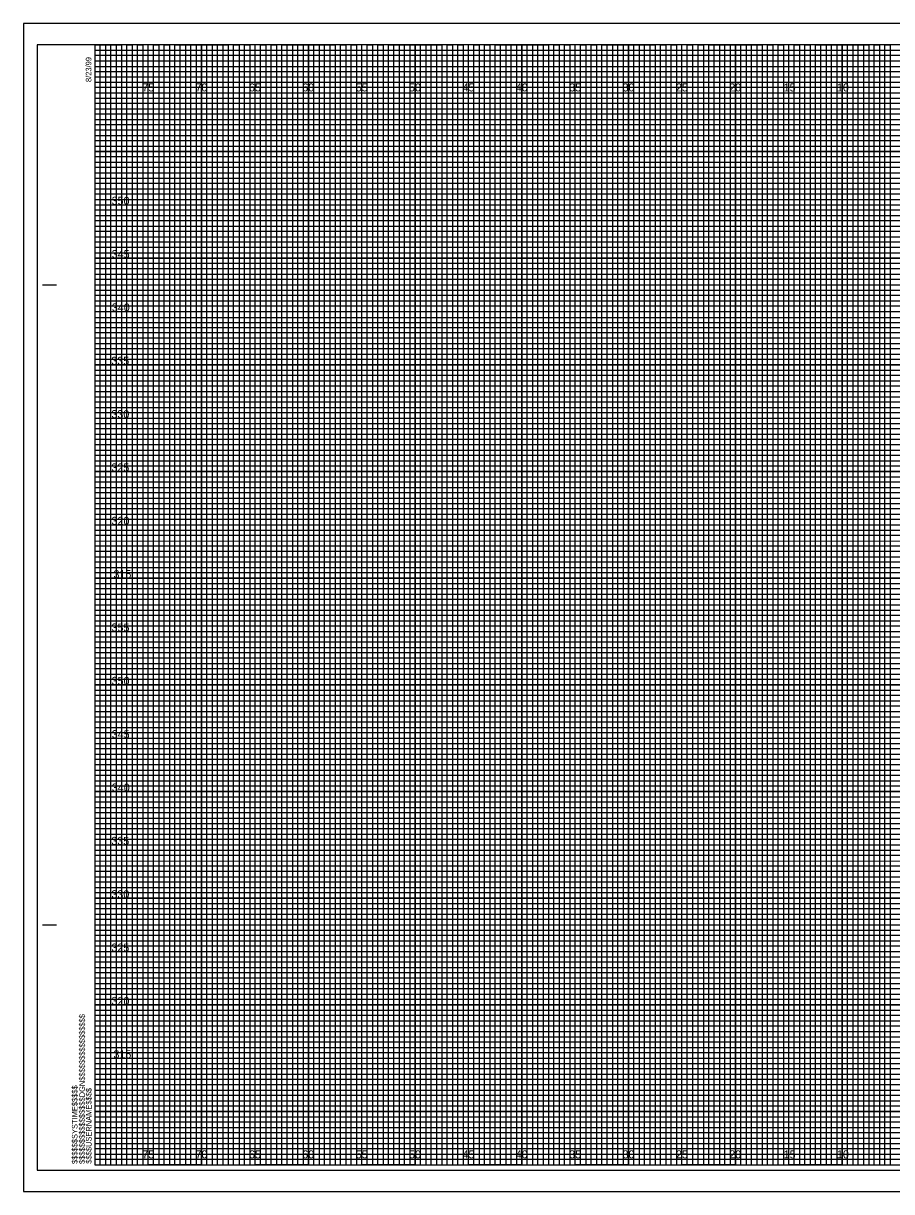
# Model space of a CAD drawing. Extents: x -7 to 162, y -2 to 327.
# Drawn here: x -6.7 to 74.6, y 107.5 to 217 of the extents above; entities that cross this region are included whole.
import ezdxf

# ---------------------------------------------------------------- set-up
doc = ezdxf.new("R2010")
doc.units = 0
for name, color, linetype in [('Exist Cross Section Cell', 7, 'Continuous'), ('Exist XS Center Line Elevation Label', 7, 'Continuous'), ('Exist XS Ground Line', 7, 'Continuous'), ('Old_Level_1', 7, 'Continuous'), ('Prop XS Bridge', 7, 'Continuous'), ('Prop XS Ditch Standard Text', 7, 'Continuous'), ('Prop XS EOT Tick Mark', 7, 'Continuous'), ('Prop XS Finish Grade Earthwork', 7, 'Continuous'), ('Prop XS Label Text', 7, 'Continuous'), ('Prop XS Subgrade', 7, 'Continuous'), ('Scratch_Level_3', 7, 'Continuous')]:
    doc.layers.add(name, color=color, linetype=linetype)

msp = doc.modelspace()

# ---------------------------------------------------------------- linework, layer by layer
at = {"layer": 'Exist XS Center Line Elevation Label'}
for points in [[(0, 215), (2.5, 215), (2.5, 110), (7.5, 110), (7.5, 215), (12.5, 215), (12.5, 110), (17.5, 110), (17.5, 215), (22.5, 215), (22.5, 110), (27.5, 110), (27.5, 215), (32.5, 215), (32.5, 110), (37.5, 110), (37.5, 215), (42.5, 215), (42.5, 110), (47.5, 110), (47.5, 215), (52.5, 215), (52.5, 110), (57.5, 110), (57.5, 215), (62.5, 215), (62.5, 110), (67.5, 110), (67.5, 215), (72.5, 215), (72.5, 110), (77.5, 110)], [(0, 212.5), (137.5, 212.5)], [(0, 202.5), (160, 202.5), (160, 207.5), (0, 207.5)], [(0, 192.5), (160, 192.5), (160, 197.5), (0, 197.5)], [(0, 182.5), (160, 182.5), (160, 187.5), (0, 187.5)], [(0, 172.5), (160, 172.5), (160, 177.5), (0, 177.5)], [(0, 162.5), (160, 162.5), (160, 167.5), (0, 167.5)], [(0, 152.5), (160, 152.5), (160, 157.5), (0, 157.5)], [(0, 142.5), (160, 142.5), (160, 147.5), (0, 147.5)], [(0, 132.5), (160, 132.5), (160, 137.5), (0, 137.5)], [(0, 122.5), (160, 122.5), (160, 127.5), (0, 127.5)], [(0, 112.5), (160, 112.5), (160, 117.5), (0, 117.5)]]:
    msp.add_lwpolyline(points, dxfattribs=at)
at = {"layer": 'Exist XS Ground Line'}
for p, q in [((5, 215), (0, 215)), ((5, 110), (5, 215)), ((15, 215), (10, 215)), ((10, 215), (10, 110)), ((15, 110), (15, 215)), ((25, 215), (20, 215)), ((20, 215), (20, 110)), ((25, 110), (25, 215)), ((35, 215), (30, 215)), ((30, 215), (30, 110)), ((35, 110), (35, 215)), ((45, 215), (40, 215)), ((40, 215), (40, 110)), ((45, 110), (45, 215)), ((55, 215), (50, 215)), ((50, 215), (50, 110)), ((55, 110), (55, 215)), ((65, 215), (60, 215)), ((60, 215), (60, 110)), ((65, 110), (65, 215)), ((75, 215), (70, 215)), ((70, 215), (70, 110)), ((10, 110), (5, 110)), ((20, 110), (15, 110)), ((30, 110), (25, 110)), ((40, 110), (35, 110)), ((50, 110), (45, 110)), ((60, 110), (55, 110)), ((70, 110), (65, 110))]:
    msp.add_line(p, q, dxfattribs=at)
for points in [[(0, 210), (160, 210), (160, 205), (0, 205)], [(0, 200), (160, 200), (160, 195), (0, 195)], [(0, 190), (160, 190), (160, 185), (0, 185)], [(0, 180), (160, 180), (160, 175), (0, 175)], [(0, 170), (160, 170), (160, 165), (0, 165)], [(0, 160), (160, 160), (160, 155), (0, 155)], [(0, 150), (160, 150), (160, 145), (0, 145)], [(0, 140), (160, 140), (160, 135), (0, 135)], [(0, 130), (160, 130), (160, 125), (0, 125)], [(0, 120), (160, 120), (160, 115), (0, 115)]]:
    msp.add_lwpolyline(points, dxfattribs=at)
at = {"layer": 'Old_Level_1'}
msp.add_lwpolyline([(-5.4, 109.5), (161.2, 109.5), (161.2, 215), (-5.4, 215)], close=True, dxfattribs=at)
at = {"layer": 'Prop XS Bridge'}
for p, q in [((5, 110), (5, 215)), ((10, 110), (10, 215)), ((15, 110), (15, 215)), ((20, 110), (20, 215)), ((25, 110), (25, 215)), ((30, 110), (30, 215)), ((35, 110), (35, 215)), ((40, 110), (40, 215)), ((45, 110), (45, 215)), ((50, 110), (50, 215)), ((55, 110), (55, 215)), ((60, 110), (60, 215)), ((65, 110), (65, 215)), ((70, 110), (70, 215)), ((0, 210), (160, 210)), ((0, 205), (160, 205)), ((0, 200), (160, 200)), ((0, 195), (160, 195)), ((0, 190), (160, 190)), ((0, 185), (160, 185)), ((0, 180), (160, 180)), ((0, 175), (160, 175)), ((0, 170), (160, 170)), ((0, 165), (160, 165)), ((0, 160), (160, 160)), ((0, 155), (160, 155)), ((0, 150), (160, 150)), ((0, 145), (160, 145)), ((0, 140), (160, 140)), ((0, 135), (160, 135)), ((0, 130), (160, 130)), ((0, 125), (160, 125)), ((0, 120), (160, 120)), ((0, 115), (160, 115))]:
    msp.add_line(p, q, dxfattribs=at)
at = {"layer": 'Prop XS EOT Tick Mark'}
for p, q in [((-4.9, 192.5), (-3.65, 192.5)), ((-4.85, 192.5), (-3.6, 192.5)), ((-4.9, 132.5), (-3.65, 132.5)), ((-4.85, 132.5), (-3.6, 132.5)), ((0, 110), (0, 110)), ((0, 110), (0, 110)), ((0, 110), (0, 110)), ((0, 110), (0, 110)), ((0, 110), (0, 110)), ((0, 110), (0, 110)), ((0, 110), (0, 110))]:
    msp.add_line(p, q, dxfattribs=at)
msp.add_lwpolyline([(160, 215), (0, 215), (0, 110), (160, 110)], close=True, dxfattribs=at)
at = {"layer": 'Prop XS Finish Grade Earthwork'}
for p, q in [((161.65, 217), (-6.7, 217)), ((-6.7, 217), (-6.7, 107.5)), ((-6.7, 107.5), (161.65, 107.5))]:
    msp.add_line(p, q, dxfattribs=at)
at = {"layer": 'Prop XS Label Text'}
for points in [[(0, 110), (0.5, 110), (0.5, 215), (1, 215), (1, 110)], [(1, 110), (1.5, 110), (1.5, 215), (2, 215), (2, 110)], [(2.5, 110), (3, 110), (3, 215), (3.5, 215), (3.5, 110)], [(3.5, 110), (4, 110), (4, 215), (4.5, 215), (4.5, 110)], [(5, 110), (5.5, 110), (5.5, 215), (6, 215), (6, 110)], [(6, 110), (6.5, 110), (6.5, 215), (7, 215), (7, 110)], [(7.5, 110), (8, 110), (8, 215), (8.5, 215), (8.5, 110)], [(8.5, 110), (9, 110), (9, 215), (9.5, 215), (9.5, 110)], [(10, 110), (10.5, 110), (10.5, 215), (11, 215), (11, 110)], [(11, 110), (11.5, 110), (11.5, 215), (12, 215), (12, 110)], [(12.5, 110), (13, 110), (13, 215), (13.5, 215), (13.5, 110)], [(13.5, 110), (14, 110), (14, 215), (14.5, 215), (14.5, 110)], [(15, 110), (15.5, 110), (15.5, 215), (16, 215), (16, 110)], [(16, 110), (16.5, 110), (16.5, 215), (17, 215), (17, 110)], [(17.5, 110), (18, 110), (18, 215), (18.5, 215), (18.5, 110)], [(18.5, 110), (19, 110), (19, 215), (19.5, 215), (19.5, 110)], [(20, 110), (20.5, 110), (20.5, 215), (21, 215), (21, 110)], [(21, 110), (21.5, 110), (21.5, 215), (22, 215), (22, 110)], [(22.5, 110), (23, 110), (23, 215), (23.5, 215), (23.5, 110)], [(23.5, 110), (24, 110), (24, 215), (24.5, 215), (24.5, 110)], [(25, 110), (25.5, 110), (25.5, 215), (26, 215), (26, 110)], [(26, 110), (26.5, 110), (26.5, 215), (27, 215), (27, 110)], [(27.5, 110), (28, 110), (28, 215), (28.5, 215), (28.5, 110)], [(28.5, 110), (29, 110), (29, 215), (29.5, 215), (29.5, 110)], [(30, 110), (30.5, 110), (30.5, 215), (31, 215), (31, 110)], [(31, 110), (31.5, 110), (31.5, 215), (32, 215), (32, 110)], [(32.5, 110), (33, 110), (33, 215), (33.5, 215), (33.5, 110)], [(33.5, 110), (34, 110), (34, 215), (34.5, 215), (34.5, 110)], [(35, 110), (35.5, 110), (35.5, 215), (36, 215), (36, 110)], [(36, 110), (36.5, 110), (36.5, 215), (37, 215), (37, 110)], [(37.5, 110), (38, 110), (38, 215), (38.5, 215), (38.5, 110)], [(38.5, 110), (39, 110), (39, 215), (39.5, 215), (39.5, 110)], [(40, 110), (40.5, 110), (40.5, 215), (41, 215), (41, 110)], [(41, 110), (41.5, 110), (41.5, 215), (42, 215), (42, 110)], [(42.5, 110), (43, 110), (43, 215), (43.5, 215), (43.5, 110)], [(43.5, 110), (44, 110), (44, 215), (44.5, 215), (44.5, 110)], [(45, 110), (45.5, 110), (45.5, 215), (46, 215), (46, 110)], [(46, 110), (46.5, 110), (46.5, 215), (47, 215), (47, 110)], [(47.5, 110), (48, 110), (48, 215), (48.5, 215), (48.5, 110)], [(48.5, 110), (49, 110), (49, 215), (49.5, 215), (49.5, 110)], [(50, 110), (50.5, 110), (50.5, 215), (51, 215), (51, 110)], [(51, 110), (51.5, 110), (51.5, 215), (52, 215), (52, 110)], [(52.5, 110), (53, 110), (53, 215), (53.5, 215), (53.5, 110)], [(53.5, 110), (54, 110), (54, 215), (54.5, 215), (54.5, 110)], [(55, 110), (55.5, 110), (55.5, 215), (56, 215), (56, 110)], [(56, 110), (56.5, 110), (56.5, 215), (57, 215), (57, 110)], [(57.5, 110), (58, 110), (58, 215), (58.5, 215), (58.5, 110)], [(58.5, 110), (59, 110), (59, 215), (59.5, 215), (59.5, 110)], [(60, 110), (60.5, 110), (60.5, 215), (61, 215), (61, 110)], [(61, 110), (61.5, 110), (61.5, 215), (62, 215), (62, 110)], [(62.5, 110), (63, 110), (63, 215), (63.5, 215), (63.5, 110)], [(63.5, 110), (64, 110), (64, 215), (64.5, 215), (64.5, 110)], [(65, 110), (65.5, 110), (65.5, 215), (66, 215), (66, 110)], [(66, 110), (66.5, 110), (66.5, 215), (67, 215), (67, 110)], [(67.5, 110), (68, 110), (68, 215), (68.5, 215), (68.5, 110)], [(68.5, 110), (69, 110), (69, 215), (69.5, 215), (69.5, 110)], [(70, 110), (70.5, 110), (70.5, 215), (71, 215), (71, 110)], [(71, 110), (71.5, 110), (71.5, 215), (72, 215), (72, 110)], [(72.5, 110), (73, 110), (73, 215), (73.5, 215), (73.5, 110)], [(73.5, 110), (74, 110), (74, 215), (74.5, 215), (74.5, 110)]]:
    msp.add_lwpolyline(points, dxfattribs=at)
at = {"layer": 'Prop XS Subgrade'}
msp.add_lwpolyline([(-6.7, 107.5), (161.65, 107.5), (161.65, 217), (-6.7, 217)], close=True, dxfattribs=at)
at = {"layer": 'Scratch_Level_3'}
for p, q in [((0, 214.5), (130, 214.5)), ((130, 213.99), (0, 213.99)), ((0, 213.99), (0, 213.5)), ((0, 213.5), (130, 213.5)), ((130, 212.94), (0, 212.94)), ((0, 212.94), (0, 212)), ((0, 212), (160, 212))]:
    msp.add_line(p, q, dxfattribs=at)
for points in [[(0, 211.5), (135, 211.5), (160, 211.5), (160, 211), (0, 211)], [(0, 210.5), (160, 210.5), (160, 209.5), (0, 209.5)], [(0, 209), (160, 209), (160, 208.5), (0, 208.49)], [(0, 208), (160, 208), (160, 207), (0, 207)], [(0, 206.5), (160, 206.5), (160, 206), (0, 206)], [(0, 205.5), (160, 205.5), (160, 204.5), (0, 204.5)], [(0, 204), (160, 204), (160, 203.5), (0, 203.5)], [(0, 203), (160, 203), (160, 202), (0, 202)], [(0, 201.5), (160, 201.5), (160, 201), (0, 201)], [(0, 200.5), (160, 200.5), (160, 199.5), (0, 199.5)], [(0, 199), (160, 199), (160, 198.5), (0, 198.5)], [(0, 198), (160, 198), (160, 196.97), (160, 196.5), (160, 196), (0, 196)], [(0, 197), (160, 197), (160, 196.5), (0, 196.5)], [(0, 195.5), (160, 195.5), (160, 194.5), (0, 194.52)], [(0, 194.52), (160, 194.5), (160, 194), (0, 194)], [(0, 193.5), (160, 193.5), (160, 193), (0, 193)], [(0, 192), (160, 192), (160, 191.5), (0, 191.5)], [(0, 191), (160, 191), (160, 190.5), (0, 190.5)], [(-0.04, 189.44), (160, 189.44), (160, 188.94), (-0.04, 188.94)], [(0, 188.5), (160, 188.5), (160, 188), (0, 188)], [(0, 187), (160, 187), (160, 186.5), (0, 186.5)], [(0, 186), (160, 186), (160, 185.5), (0, 185.5)], [(0, 184.5), (160, 184.5), (160, 184), (0, 184)], [(0, 183.5), (160, 183.5), (160, 183), (0, 183)], [(0, 182), (160, 182), (160, 181.5), (0, 181.5)], [(0, 181), (160, 181), (160, 180.5), (0, 180.5)], [(0, 179.5), (160, 179.5), (160, 178.99), (0, 179)], [(0, 178.5), (160, 178.5), (160, 178), (0, 178)], [(0, 177), (160, 177), (160, 176.5), (0, 176.5)], [(0, 176), (160, 176), (160, 175.5), (0, 175.5)], [(0, 174.5), (160, 174.5), (160, 174), (0, 174)], [(0, 173.5), (160, 173.5), (160, 173), (0, 173)], [(0, 172), (160, 172), (160, 171.5), (0, 171.5)], [(0, 171), (160, 171), (160, 170.5), (0, 170.5)], [(0, 169.5), (160, 169.5), (160, 169), (0, 169)], [(0, 168.5), (160.03, 168.46), (160, 168), (0, 168)], [(0, 167), (160, 167), (160, 166.5), (0, 166.5)], [(0, 166), (160, 166), (160, 165.5), (0, 165.5)], [(0, 164.5), (160, 164.5), (160, 164), (0, 164)], [(0, 163.5), (160, 163.5), (160, 163), (0, 163)], [(0, 162), (160, 162), (160, 161.5), (0, 161.5)], [(0, 161), (160, 161), (160, 160.5), (0, 160.5)], [(0, 159.5), (160, 159.5), (160, 159), (0, 159)], [(0, 158.5), (160, 158.5), (160, 158), (0, 158)], [(0, 157), (160, 157), (160, 156.5), (0, 156.5)], [(0, 156), (160, 156), (160, 155.5), (0, 155.5)], [(0, 154.5), (160, 154.5), (160, 154), (0, 154)], [(0, 153.5), (160, 153.5), (160, 153), (0, 153)], [(0, 152), (160, 152), (160, 151.5), (0, 151.5)], [(0, 151), (160, 151), (160, 150.5), (0, 150.5)], [(0, 149.5), (160, 149.5), (160, 148.99), (0, 149)], [(0, 148.5), (160, 148.5), (160, 148), (0, 148)], [(0, 147), (160, 147), (160, 146.5), (0, 146.5)], [(0, 146), (160, 146), (160, 145.5), (0, 145.5)], [(0, 144.5), (160, 144.5), (160, 144), (0, 144)], [(0, 143.5), (160, 143.5), (160, 143), (0, 143)], [(0, 142), (160, 142), (160, 141.5), (0, 141.5)], [(0, 141), (160, 141), (160, 140.5), (0, 140.5)], [(0, 139.5), (160, 139.5), (160, 139), (0, 139)], [(0, 138.5), (160.03, 138.46), (160, 138), (0, 138)], [(0, 137), (160, 137), (160, 136.5), (0, 136.5)], [(0, 136), (160, 136), (160, 135.5), (0, 135.5)], [(0, 134.5), (160, 134.5), (160, 134), (0, 134)], [(0, 133.5), (160, 133.5), (160, 133), (0, 133)], [(0, 132), (160, 132), (160, 131.5), (0, 131.5)], [(0, 131), (160, 131), (160, 130.5), (0, 130.5)], [(0, 129.5), (160, 129.5), (160, 129), (0, 129)], [(0, 128.5), (160, 128.5), (160, 128), (0, 128)], [(0, 127), (160, 127), (160, 126.5), (0, 126.5)], [(0, 126), (160, 126), (160, 125.5), (0, 125.5)], [(0, 124.5), (160, 124.5), (160, 124), (0, 124)], [(0, 123.5), (160, 123.5), (160, 123), (0, 123)], [(0, 122), (160, 122), (160, 121.5), (0, 121.5)], [(0, 121), (160, 121), (160, 120.5), (0, 120.5)], [(0, 119.5), (160, 119.5), (160, 119), (0, 119)], [(0, 118.5), (160, 118.5), (160, 118), (0, 118)], [(0, 117), (160, 117), (160, 116.5), (0, 116.5)], [(0, 116), (160, 116), (160, 115.5), (0, 115.5)], [(0, 114.5), (160, 114.5), (160, 114), (0, 114)], [(0, 113.5), (160, 113.5), (160, 113), (0, 113)], [(0, 112), (160, 112), (160, 111.5), (0, 111.5)], [(0, 111), (160, 111), (160, 110.5), (0, 110.5)]]:
    msp.add_lwpolyline(points, dxfattribs=at)

# ---------------------------------------------------------------- texts
at = {"layer": 'Exist Cross Section Cell'}
for s, p in [('75', (4.44, 210.62)), ('70', (9.43, 210.62)), ('65', (14.44, 210.62)), ('60', (19.43, 210.62)), ('55', (24.44, 210.62)), ('50', (29.43, 210.62)), ('45', (34.44, 210.62)), ('40', (39.43, 210.62)), ('35', (44.44, 210.62)), ('30', (49.43, 210.62)), ('25', (54.44, 210.62)), ('20', (59.43, 210.62)), ('15', (64.53, 210.62)), ('10', (69.52, 210.62)), ('75', (4.44, 110.62)), ('70', (9.43, 110.62)), ('65', (14.44, 110.62)), ('60', (19.43, 110.62)), ('55', (24.44, 110.62)), ('50', (29.43, 110.62)), ('45', (34.44, 110.62)), ('40', (39.43, 110.62)), ('35', (44.44, 110.62)), ('30', (49.43, 110.62)), ('25', (54.44, 110.62)), ('20', (59.43, 110.62)), ('15', (64.53, 110.62)), ('10', (69.52, 110.62))]:
    msp.add_text(s, height=0.75, dxfattribs=at).set_placement(p)
at = {"layer": 'Prop XS Ditch Standard Text'}
for s, p in [('350', (1.57, 200)), ('345', (1.58, 195)), ('340', (1.59, 190)), ('335', (1.54, 185)), ('330', (1.55, 180)), ('325', (1.55, 175)), ('320', (1.56, 170)), ('315', (1.74, 165)), ('355', (1.56, 160)), ('350', (1.57, 155)), ('345', (1.58, 150)), ('340', (1.59, 145)), ('335', (1.54, 140)), ('330', (1.55, 135)), ('325', (1.55, 130)), ('320', (1.56, 125)), ('315', (1.74, 120))]:
    msp.add_text(s, height=0.75, dxfattribs=at).set_placement(p)
at = {"layer": 'Prop XS EOT Tick Mark'}
for s, p in [('8/23/99', (-0.33, 211.5)), ('$$$$$$$$$$$$$$$$DGN$$$$$$$$$$$$$$$$', (-0.94, 110.09)), ('$$$$$$SYSTIME$$$$$', (-1.63, 110.09)), ('$$$$USERNAME$$$$', (-0.31, 110.12))]:
    msp.add_text(s, height=0.525, rotation=90, dxfattribs=at).set_placement(p)

doc.saveas('drawing.dxf')
